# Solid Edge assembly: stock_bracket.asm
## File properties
Author: vicky raina
Template: Normal.asm
Last saved by: CADCIM
Revision: 28
Application: Solid Edge
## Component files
adjusting_screw_guide.par
adjusting_nut_handle.par
stock_support_roller.par
Stock_support_base.par
thrust_bearing.par
adjusting_screw_nut.par
support_adjusting_screw.par
support_roller_bracket.par
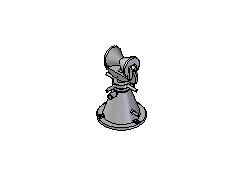
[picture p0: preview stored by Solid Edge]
